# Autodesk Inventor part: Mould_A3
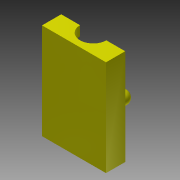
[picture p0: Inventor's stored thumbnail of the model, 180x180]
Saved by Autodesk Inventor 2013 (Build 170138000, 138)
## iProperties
Created: 2013-06
Part Number: Mould_A3
Material: Generic
Document SubType Name: Modeling
Designer: frankenteddy
Density: 1 g/cm^3
Author: frankenteddy
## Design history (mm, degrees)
sketch "Sketch1"
  geometry: L1 (-10, 12)-(10, 12); L2 (10, 12)-(10, -12); L3 (10, -12)-(-10, -12); L4 (-10, -12)-(-10, 12); L5 (-10, 12)-(-10, 15); L6 (-10, 15)-(10, 15); L7 (10, 15)-(10, 12); 3 further points
  constraints: 14 end point, 3 parallel, 2 midpoint, 2 perpendicular, 1 collinear, 1 horizontal, 1 horizontal alignment, 1 vertical alignment
  dimensions: "d0" = 24 distance of L1.end L2.end; "d2" = 20 distance of L1.start L1.end; "d65" = 3 distance of L1.start L5.end
extrude "Extrusion1" new body sketch "Sketch1" distance "d3" = 6; taper "d4" = 0 deg
workplane "Work Plane1"
sketch "Sketch2"
  geometry: L1 (-10, -12)-(10, -12) reference; L2 (5, 12)-(5, 6.138); L3 (0, 12)-(5, 12); L4 (3.5, 3.016)-(3.5, 0); L5 (3.5, 0)-(0, 0); L6 (0, 0)-(0, 12); A1 r 2 centre (5.5, 3.016) between (4.25, 4.577) and (3.5, 3.016); A2 r 2 centre (3, 6.138) between (4.25, 4.577) and (5, 6.138); 3 further points
  constraints: 10 end point, 4 point on circle, 3 perpendicular, 3 tangent, 2 centre point, 2 vertical alignment, 1 horizontal, 1 parallel
  dimensions: "d15" = 2 radius of A1; "d18" = 2 radius of A2; "d55" = 5 distance of L3.start L2.start; "d56" = 3.5 distance between parallel lines of L6 L4; "d59" = 12 distance between parallel lines of L5 L3
revolve "Revolution1" sketch "Sketch2" stored, may be unused: angle "d20" = 90 deg
mirror "Mirror1"
workplane "Work Plane2"
sketch "Sketch3"
  geometry: L1 (-17.279, 0)-(16.833, 0) reference; L2 (0, 16.632)-(0, -16.118) reference; L3 (17.279, 0)-(-16.833, 0); L4 (-1, 9)-(-3, 9); L5 (-3, 9)-(-3, 8); L6 (-3, 8)-(-1, 8); L7 (-1, 8)-(-1, 9); C1 r 2 at (-7, 0); C2 r 2.2 at (7, 0); 1 further point
  constraints: 14 end point, 3 horizontal, 2 centre point, 2 parallel, 2 perpendicular, 2 symmetric about line, 1 vertical
  dimensions: "d24" = 4 diameter of C1; "d26" = 0 vertical distance of point (0, 0) C1.centre; "d27" = 7 distance of point (0, 0) C1.centre; "d36" = 4.4 diameter of C2; "d37" = 7 distance from line of L2 C2.centre; "d38" = 0 distance from line of L1 C2.centre; "d47" = 2 distance of L6.end L5.end; "d48" = 1 distance of L5.end L4.end; "d49" = 1 distance between parallel lines of L2 L7; "d50" = 8 distance between parallel lines of L1 L6
extrude "Extrusion6" join sketch "Sketch3" distance "d60" = 4; taper "d61" = 0 deg
extrude "Extrusion7" cut sketch "Sketch3" distance "d62" = 4; taper "d63" = 0 deg
fillet "Fillet3" dims "d64" = 2
extrude "Extrusion8" join sketch "Sketch1" distance "d66" = 6; taper "d67" = 0 deg
workplane "Work Plane3"
sketch "Sketch5"
  geometry: L1 (0, 15)-(4.1, 15); L2 (4.1, 15)-(4.1, 12); L3 (4.1, 12)-(0, 12); L4 (0, 12)-(0, 15); 1 further point
  constraints: 8 end point, 2 parallel, 1 horizontal, 1 perpendicular
  dimensions: "d71" = 4.1 distance of L2.end L3.end; "d72" = 3 distance of L1.end L2.end; "d73" = 12 distance from line of L3 point (0, 0)
revolve "Revolution4" sketch "Sketch5" stored, may be unused: angle "d74" = 90 deg
mirror "Mirror3"
body "Solid1"
other parameters: "d5" = 6, "d23" = 6, "d70" = 6
